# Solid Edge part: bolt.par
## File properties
Author: Sarvanan
Template: sync ansi part.par
Last saved by: TIET
Revision: 6
Application: Solid Edge
Accuracy: 0.990
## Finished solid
Body 1: solid body, 11 faces, 21 edges, 12 vertices.
  Faces by surface: plane 9, cone 1, cylinder 1
  Edges by curve: line 12, intersection 6, circle 3
Bounding box of the edges (mm): 7.620 x 8.799 x 81.280, from (-0.0184, -5.4708, -78.74) to (7.6016, 3.328, 2.54).
Cylindrical faces by radius (mm): R3.3834 x1
Conical faces (half-angle, radius in mm at the cone's reference point): 45 deg R4.3994 x1
Planar faces by outward normal: +x 1, +z 1, -x 1, -z 2, oblique 4
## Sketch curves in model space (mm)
circle centre (3.7916, -1.0714, 2.54) radius 3.302
line (3.7916, -1.0714, 2.54) -> (7.175, -1.0714, 2.54)
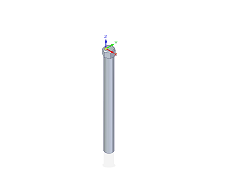
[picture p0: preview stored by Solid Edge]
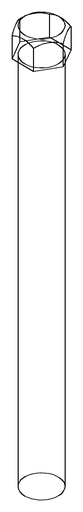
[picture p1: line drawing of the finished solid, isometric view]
